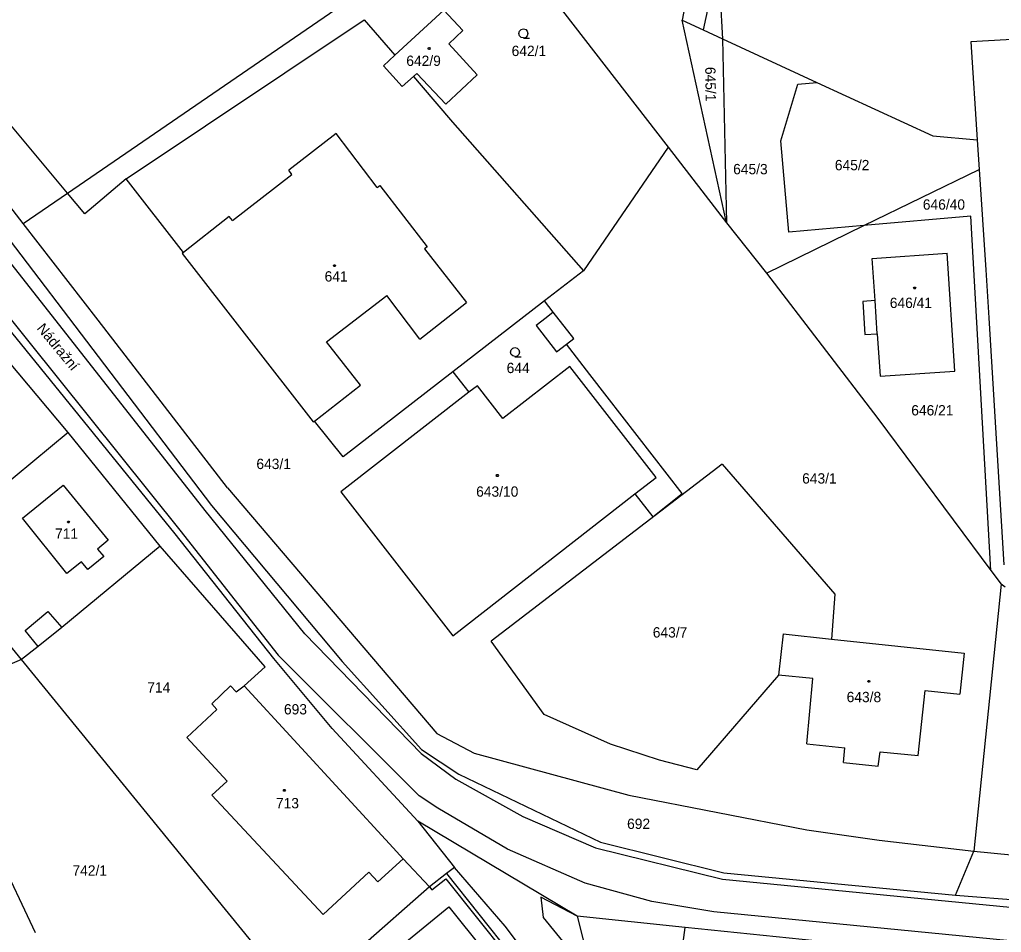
# Model space of a CAD drawing. Extents: x -621797 to -620972, y -1175539 to -1174697.
# Drawn here: x -621313.4 to -621151.7, y -1175130.5 to -1174980.1 of the extents above; entities that cross this region are included whole.
import ezdxf

# ---------------------------------------------------------------- set-up
doc = ezdxf.new("R2010")
doc.units = 0
for name, color, linetype in [('INZ mimo EON - nadz', 7, 'Continuous'), ('Rozvod plynu EON', 7, 'Continuous'), ('SDEL EON', 7, 'Continuous'), ('SDEL EON - popis', 7, 'Continuous'), ('Silnoproud EON', 7, 'Continuous'), ('Silnoproud EON - popis', 7, 'Continuous')]:
    doc.layers.add(name, color=color, linetype=linetype)

msp = doc.modelspace()

# ---------------------------------------------------------------- linework, layer by layer
at = {"layer": 'Rozvod plynu EON'}
for points in [[(-621245.87, -1174984.67), (-621245.78, -1174984.82), (-621245.87, -1174984.97), (-621246.05, -1174984.97), (-621246.14, -1174984.82), (-621246.05, -1174984.67)], [(-621261.45, -1175020.49), (-621261.36, -1175020.64), (-621261.45, -1175020.79), (-621261.63, -1175020.79), (-621261.72, -1175020.64), (-621261.63, -1175020.49)], [(-621165.88, -1175024.17), (-621165.79, -1175024.32), (-621165.88, -1175024.47), (-621166.06, -1175024.47), (-621166.15, -1175024.32), (-621166.06, -1175024.17)], [(-621234.62, -1175055.08), (-621234.53, -1175055.23), (-621234.62, -1175055.38), (-621234.8, -1175055.38), (-621234.89, -1175055.23), (-621234.8, -1175055.08)], [(-621305.29, -1175062.75), (-621305.2, -1175062.9), (-621305.29, -1175063.05), (-621305.47, -1175063.05), (-621305.56, -1175062.9), (-621305.47, -1175062.75)], [(-621173.42, -1175089.01), (-621173.33, -1175089.16), (-621173.42, -1175089.31), (-621173.6, -1175089.31), (-621173.69, -1175089.16), (-621173.6, -1175089.01)], [(-621269.73, -1175106.96), (-621269.64, -1175107.11), (-621269.73, -1175107.26), (-621269.91, -1175107.26), (-621270, -1175107.11), (-621269.91, -1175106.96)]]:
    msp.add_lwpolyline(points, close=True, dxfattribs=at)
at = {"layer": 'SDEL EON'}
for points in [[(-621230.41, -1174983.09), (-621230.79, -1174982.99), (-621231.06, -1174982.72), (-621231.16, -1174982.35), (-621231.06, -1174981.98), (-621230.79, -1174981.71), (-621230.42, -1174981.61), (-621230.05, -1174981.71), (-621229.78, -1174981.98), (-621229.68, -1174982.36), (-621229.78, -1174982.74), (-621230.05, -1174983.01), (-621230.43, -1174983.11), (-621229.43, -1174983.11)], [(-621231.8, -1175035.62), (-621232.18, -1175035.52), (-621232.45, -1175035.25), (-621232.55, -1175034.88), (-621232.45, -1175034.51), (-621232.18, -1175034.24), (-621231.81, -1175034.14), (-621231.44, -1175034.24), (-621231.17, -1175034.51), (-621231.07, -1175034.89), (-621231.17, -1175035.27), (-621231.44, -1175035.54), (-621231.82, -1175035.64), (-621230.82, -1175035.64)]]:
    msp.add_lwpolyline(points, dxfattribs=at)
at = {"layer": 'SDEL EON - popis'}
for p, q in [((-621261.29, -1174998.86), (-621269.07, -1175004.9)), ((-621254.51, -1175007.76), (-621261.29, -1174998.86)), ((-621268.57, -1175005.61), (-621269.07, -1175004.9)), ((-621278.34, -1175013.19), (-621268.57, -1175005.61)), ((-621254.51, -1175007.76), (-621254.09, -1175007.44)), ((-621254.09, -1175007.44), (-621246.3, -1175017.54)), ((-621282.85, -1175060.98), (-621323.62, -1175009.12)), ((-621328.01, -1175013.22), (-621287.02, -1175064.24)), ((-621278.89, -1175012.55), (-621286.44, -1175018.46)), ((-621278.34, -1175013.19), (-621278.89, -1175012.55)), ((-621246.3, -1175017.54), (-621246.7, -1175017.85)), ((-621246.7, -1175017.85), (-621239.78, -1175026.69)), ((-621262.87, -1175033.19), (-621252.95, -1175025.52)), ((-621247.47, -1175032.72), (-621252.95, -1175025.52)), ((-621172.13, -1175031.86), (-621172.49, -1175026.37)), ((-621247.47, -1175032.72), (-621239.78, -1175026.69)), ((-621226.69, -1175029.21), (-621228.3, -1175030.51)), ((-621225.53, -1175028.27), (-621226.69, -1175029.21)), ((-621228.3, -1175030.51), (-621224.96, -1175034.83)), ((-621257.28, -1175040.33), (-621262.87, -1175033.19)), ((-621224.96, -1175034.83), (-621223.33, -1175033.56)), ((-621264.86, -1175046.24), (-621257.28, -1175040.33)), ((-621266.43, -1175081.31), (-621282.85, -1175060.98)), ((-621287.02, -1175064.24), (-621270.85, -1175084.82)), ((-621312.52, -1175080.78), (-621308.77, -1175077.63)), ((-621308.77, -1175077.63), (-621306.48, -1175080.26)), ((-621310.35, -1175083.43), (-621312.52, -1175080.78)), ((-621247.27, -1175101.06), (-621266.43, -1175081.31)), ((-621270.85, -1175084.82), (-621247.62, -1175108.02)), ((-621247.27, -1175101.06), (-621241.56, -1175105.27)), ((-621241.56, -1175105.27), (-621230.52, -1175111.43)), ((-621244.52, -1175110.05), (-621247.62, -1175108.02)), ((-621233.06, -1175116.83), (-621244.52, -1175110.05)), ((-621230.52, -1175111.43), (-621218.54, -1175116.62)), ((-621220.23, -1175122.42), (-621233.06, -1175116.83)), ((-621218.54, -1175116.62), (-621197.6, -1175121.77)), ((-621233.41, -1175129.53), (-621241.77, -1175119.82)), ((-621245.52, -1175123.51), (-621243.2, -1175121.7)), ((-621243.2, -1175121.7), (-621229.98, -1175138.22)), ((-621197.6, -1175121.77), (-621081.88, -1175133.05)), ((-621245.89, -1175123.03), (-621245.52, -1175123.51)), ((-621209.29, -1175125.46), (-621220.23, -1175122.42)), ((-621221.57, -1175127.89), (-621227.58, -1175124.71)), ((-621227.58, -1175124.71), (-621227.17, -1175128.08)), ((-621251.77, -1175133.76), (-621242.73, -1175126.34)), ((-621242.73, -1175126.34), (-621236.94, -1175133.53)), ((-621199.05, -1175127.17), (-621209.29, -1175125.46)), ((-621227.17, -1175128.08), (-621222.79, -1175133.49)), ((-621082.31, -1175138.52), (-621199.05, -1175127.17)), ((-621219.21, -1175148.23), (-621233.41, -1175129.53))]:
    msp.add_line(p, q, dxfattribs=at)
at = {"layer": 'Silnoproud EON'}
for p, q in [((-621253.29, -1174940.71), (-621206.58, -1175001.12)), ((-621199.2, -1174954.76), (-621204.28, -1174980.15)), ((-621305.54, -1175008.66), (-621247.85, -1174969.05)), ((-621198.35, -1174970.23), (-621200.83, -1174981.75)), ((-621198.35, -1174970.23), (-621197.63, -1174983.23)), ((-621243.52, -1174978.48), (-621251.59, -1174985.95)), ((-621240.39, -1174981.87), (-621243.52, -1174978.48)), ((-621295.86, -1175006.29), (-621256.67, -1174980.09)), ((-621256.67, -1174980.09), (-621251.59, -1174985.95)), ((-621204.28, -1174980.15), (-621200.83, -1174981.75)), ((-621196.98, -1175013.54), (-621204.28, -1174980.15)), ((-621095.2, -1174980.47), (-621156.69, -1174983.71)), ((-621305.54, -1175008.66), (-621327.66, -1174982.17)), ((-621242.73, -1174984.08), (-621240.39, -1174981.87)), ((-621200.83, -1174981.75), (-621197.63, -1174983.23)), ((-621238.02, -1174989.19), (-621242.73, -1174984.08)), ((-621197.63, -1174983.23), (-621182.06, -1174990.42)), ((-621197.63, -1174983.23), (-621196.98, -1175013.54)), ((-621156.69, -1174983.71), (-621155.64, -1174999.86)), ((-621251.59, -1174985.95), (-621253.49, -1174987.71)), ((-621253.49, -1174987.71), (-621250.38, -1174991.11)), ((-621248.55, -1174989.46), (-621247.99, -1174988.95)), ((-621247.99, -1174988.95), (-621243.23, -1174994.03)), ((-621243.23, -1174994.03), (-621238.02, -1174989.19)), ((-621250.38, -1174991.11), (-621248.55, -1174989.46)), ((-621248.55, -1174989.46), (-621247.29, -1174990.91)), ((-621247.29, -1174990.91), (-621242.11, -1174996.97)), ((-621188, -1175000.05), (-621185.22, -1174990.72)), ((-621185.22, -1174990.72), (-621182.06, -1174990.42)), ((-621182.06, -1174990.42), (-621162.98, -1174999.23)), ((-621312.83, -1175013.67), (-621329.73, -1174991.82)), ((-621332.26, -1174993.86), (-621281.81, -1175060.17)), ((-621242.11, -1174996.97), (-621220.55, -1175021.49)), ((-621186.67, -1175015.1), (-621188, -1175000.05)), ((-621162.98, -1174999.23), (-621155.64, -1174999.86)), ((-621155.64, -1174999.86), (-621155.32, -1175004.76)), ((-621206.58, -1175001.12), (-621220.55, -1175021.49)), ((-621206.58, -1175001.12), (-621196.98, -1175013.54)), ((-621174.32, -1175014.02), (-621155.32, -1175004.76)), ((-621155.32, -1175004.76), (-621154.25, -1175021.34)), ((-621295.86, -1175006.29), (-621302.68, -1175012.08)), ((-621286.44, -1175018.46), (-621295.86, -1175006.29)), ((-621312.83, -1175013.67), (-621305.54, -1175008.66)), ((-621302.68, -1175012.08), (-621305.54, -1175008.66)), ((-621196.98, -1175013.54), (-621190.4, -1175021.86)), ((-621156.7, -1175012.47), (-621174.32, -1175014.02)), ((-621153.4, -1175070.9), (-621156.7, -1175012.47)), ((-621300.47, -1175029.64), (-621312.83, -1175013.67)), ((-621190.4, -1175021.86), (-621174.32, -1175014.02)), ((-621174.32, -1175014.02), (-621186.67, -1175015.1)), ((-621286.44, -1175018.46), (-621286.63, -1175018.61)), ((-621286.63, -1175018.61), (-621265.04, -1175046.38)), ((-621172.95, -1175019.42), (-621160.6, -1175018.57)), ((-621172.49, -1175026.37), (-621172.95, -1175019.42)), ((-621159.32, -1175038.04), (-621160.6, -1175018.57)), ((-621220.55, -1175021.49), (-621226.95, -1175026.44)), ((-621154.25, -1175021.34), (-621153.77, -1175029.25)), ((-621190.4, -1175021.86), (-621172.02, -1175045.84)), ((-621226.95, -1175026.44), (-621242.07, -1175038.14)), ((-621225.53, -1175028.27), (-621226.95, -1175026.44)), ((-621172.49, -1175026.37), (-621174.5, -1175026.53)), ((-621174.5, -1175026.53), (-621174.17, -1175031.99)), ((-621287.81, -1175064.86), (-621318.03, -1175027.56)), ((-621279.17, -1175057.23), (-621300.47, -1175029.64)), ((-621222.14, -1175032.65), (-621225.53, -1175028.27)), ((-621153.77, -1175029.25), (-621151.28, -1175069.94)), ((-621305.4, -1175048.11), (-621320.75, -1175029.91)), ((-621223.33, -1175033.56), (-621222.14, -1175032.65)), ((-621174.17, -1175031.99), (-621172.13, -1175031.86)), ((-621172.13, -1175031.86), (-621171.67, -1175038.87)), ((-621219.46, -1175038.56), (-621223.33, -1175033.56)), ((-621222.77, -1175037.23), (-621233.84, -1175045.84)), ((-621208.54, -1175055.53), (-621222.77, -1175037.23)), ((-621242.07, -1175038.14), (-621260.12, -1175052.12)), ((-621242.07, -1175038.14), (-621239.4, -1175041.51)), ((-621216.63, -1175042.24), (-621219.46, -1175038.56)), ((-621171.67, -1175038.87), (-621159.32, -1175038.04)), ((-621238.01, -1175040.43), (-621239.4, -1175041.51)), ((-621233.84, -1175045.84), (-621238.01, -1175040.43)), ((-621239.4, -1175041.51), (-621260.52, -1175057.92)), ((-621204.29, -1175058.2), (-621216.63, -1175042.24)), ((-621172.02, -1175045.84), (-621153.4, -1175070.9)), ((-621265.04, -1175046.38), (-621264.86, -1175046.24)), ((-621260.12, -1175052.12), (-621264.86, -1175046.24)), ((-621305.4, -1175048.11), (-621324.69, -1175064.07)), ((-621290.28, -1175066.85), (-621305.4, -1175048.11)), ((-621197.67, -1175053.35), (-621235.71, -1175082.51)), ((-621197.67, -1175053.35), (-621179.12, -1175074.79)), ((-621212.04, -1175058.26), (-621208.54, -1175055.53)), ((-621312.97, -1175062.28), (-621306.25, -1175056.82)), ((-621306.25, -1175056.82), (-621298.85, -1175065.87)), ((-621279.17, -1175057.23), (-621244.69, -1175097.76)), ((-621260.52, -1175057.92), (-621242.04, -1175081.63)), ((-621242.04, -1175081.63), (-621212.04, -1175058.26)), ((-621212.04, -1175058.26), (-621209.12, -1175062.03)), ((-621209.12, -1175062.03), (-621204.29, -1175058.2)), ((-621281.81, -1175060.17), (-621260.27, -1175085.89)), ((-621305.62, -1175071.4), (-621312.97, -1175062.28)), ((-621271.56, -1175085.38), (-621287.81, -1175064.86)), ((-621290.28, -1175066.85), (-621306.48, -1175080.26)), ((-621298.85, -1175065.87), (-621300.57, -1175067.35)), ((-621272.98, -1175086.78), (-621290.28, -1175066.85)), ((-621299.57, -1175068.55), (-621302.21, -1175070.71)), ((-621300.57, -1175067.35), (-621299.57, -1175068.55)), ((-621313.11, -1175085.57), (-621326.36, -1175069.44)), ((-621303.23, -1175069.45), (-621305.62, -1175071.4)), ((-621302.21, -1175070.71), (-621303.23, -1175069.45)), ((-621153.4, -1175070.9), (-621151.72, -1175073.16)), ((-621151.72, -1175073.16), (-621156.24, -1175117.16)), ((-621151.05, -1175073.63), (-621151.72, -1175073.16)), ((-621179.12, -1175074.79), (-621179.69, -1175082.18)), ((-621306.48, -1175080.26), (-621310.35, -1175083.43)), ((-621187.65, -1175081.34), (-621188.4, -1175088.13)), ((-621187.65, -1175081.34), (-621179.69, -1175082.18)), ((-621226.99, -1175094.62), (-621235.71, -1175082.51)), ((-621179.69, -1175082.18), (-621157.8, -1175084.49)), ((-621310.35, -1175083.43), (-621313.11, -1175085.57)), ((-621157.8, -1175084.49), (-621158.53, -1175091.29)), ((-621313.11, -1175085.57), (-621328.99, -1175092.21)), ((-621267.53, -1175141.41), (-621313.11, -1175085.57)), ((-621261.94, -1175096.92), (-621271.56, -1175085.38)), ((-621260.27, -1175085.89), (-621247.24, -1175100.37)), ((-621276.45, -1175089.89), (-621272.98, -1175086.78)), ((-621188.4, -1175088.13), (-621201.83, -1175103.74)), ((-621182.76, -1175088.71), (-621188.4, -1175088.13)), ((-621183.72, -1175099.47), (-621182.76, -1175088.71)), ((-621281.78, -1175092.88), (-621278.69, -1175089.9)), ((-621278.69, -1175089.9), (-621277.75, -1175090.91)), ((-621277.75, -1175090.91), (-621276.45, -1175089.89)), ((-621251.9, -1175116.6), (-621276.45, -1175089.89)), ((-621165.4, -1175101.39), (-621164.24, -1175090.68)), ((-621164.24, -1175090.68), (-621158.53, -1175091.29)), ((-621285.9, -1175098.43), (-621280.91, -1175093.82)), ((-621280.91, -1175093.82), (-621281.78, -1175092.88)), ((-621216.09, -1175099.53), (-621226.99, -1175094.62)), ((-621247.82, -1175112.2), (-621261.94, -1175096.92)), ((-621279.24, -1175105.59), (-621285.9, -1175098.43)), ((-621244.69, -1175097.76), (-621238.56, -1175100.99)), ((-621247.24, -1175100.37), (-621241.05, -1175104.45)), ((-621208.01, -1175102.13), (-621216.09, -1175099.53)), ((-621183.72, -1175099.47), (-621177.45, -1175100.13)), ((-621177.7, -1175102.51), (-621177.45, -1175100.13)), ((-621171.95, -1175103.12), (-621171.63, -1175100.78)), ((-621171.63, -1175100.78), (-621165.4, -1175101.39)), ((-621238.56, -1175100.99), (-621213.07, -1175107.91)), ((-621201.83, -1175103.74), (-621208.01, -1175102.13)), ((-621177.7, -1175102.51), (-621171.95, -1175103.12)), ((-621281.73, -1175107.91), (-621279.24, -1175105.59)), ((-621241.05, -1175104.45), (-621217.72, -1175115.67)), ((-621263.44, -1175127.58), (-621281.73, -1175107.91)), ((-621213.07, -1175107.91), (-621183.72, -1175113.65)), ((-621247.82, -1175112.2), (-621241.77, -1175119.82)), ((-621221.57, -1175127.89), (-621247.82, -1175112.2)), ((-621183.72, -1175113.65), (-621171.81, -1175115.32)), ((-621171.81, -1175115.32), (-621156.24, -1175117.16)), ((-621317.61, -1175116.28), (-621310.86, -1175130.56)), ((-621250.23, -1175118.39), (-621251.9, -1175116.6)), ((-621217.72, -1175115.67), (-621197.4, -1175120.74)), ((-621250.23, -1175118.39), (-621254.39, -1175122.22)), ((-621245.89, -1175123.03), (-621250.23, -1175118.39)), ((-621159.25, -1175124.41), (-621156.24, -1175117.16)), ((-621156.24, -1175117.16), (-621150.08, -1175117.76)), ((-621241.77, -1175119.82), (-621243.11, -1175120.86)), ((-621255.87, -1175120.61), (-621263.44, -1175127.58)), ((-621254.39, -1175122.22), (-621255.87, -1175120.61)), ((-621243.11, -1175120.86), (-621245.89, -1175123.03)), ((-621243.11, -1175120.86), (-621229.53, -1175137.85)), ((-621197.4, -1175120.74), (-621159.25, -1175124.41)), ((-621245.89, -1175123.03), (-621257.36, -1175133.16)), ((-621159.25, -1175124.41), (-621147.63, -1175125.29)), ((-621203.79, -1175129.72), (-621221.57, -1175127.89)), ((-621221.57, -1175127.89), (-621220.4, -1175132.44)), ((-621204.25, -1175133.44), (-621203.79, -1175129.72)), ((-621178.07, -1175132.39), (-621203.79, -1175129.72))]:
    msp.add_line(p, q, dxfattribs=at)

# ---------------------------------------------------------------- texts
at = {"layer": 'INZ mimo EON - nadz'}
msp.add_text('Nádražní', height=1.7, rotation=309.62639, dxfattribs=at).set_placement((-621310.682, -1175031.005))
for s, p in [('643/1', (-621274.412, -1175054.16)), ('742/1', (-621304.713, -1175121.19))]:
    msp.add_text(s, height=1.7, dxfattribs=at).set_placement(p)
at = {"layer": 'Silnoproud EON - popis'}
for s, p in [('642/1', (-621232.363, -1174986.07)), ('642/9', (-621249.717, -1174987.7)), ('645/3', (-621195.867, -1175005.56)), ('645/2', (-621179.113, -1175004.9)), ('646/40', (-621164.619, -1175011.4)), ('641', (-621263.173, -1175023.25)), ('646/41', (-621170.064, -1175027.61)), ('644', (-621233.183, -1175038.34)), ('646/21', (-621166.523, -1175045.32)), ('643/1', (-621184.503, -1175056.55)), ('643/10', (-621238.208, -1175058.72)), ('711', (-621307.583, -1175065.65)), ('643/7', (-621209.11, -1175081.93)), ('714', (-621292.393, -1175091.01)), ('643/8', (-621177.17, -1175092.59)), ('693', (-621269.873, -1175094.61)), ('713', (-621271.193, -1175110.09)), ('692', (-621213.343, -1175113.49))]:
    msp.add_text(s, height=1.7, dxfattribs=at).set_placement(p)
msp.add_text('645/1', height=1.7, rotation=270.89444, dxfattribs=at).set_placement((-621200.474, -1174987.877))

doc.saveas('drawing.dxf')
